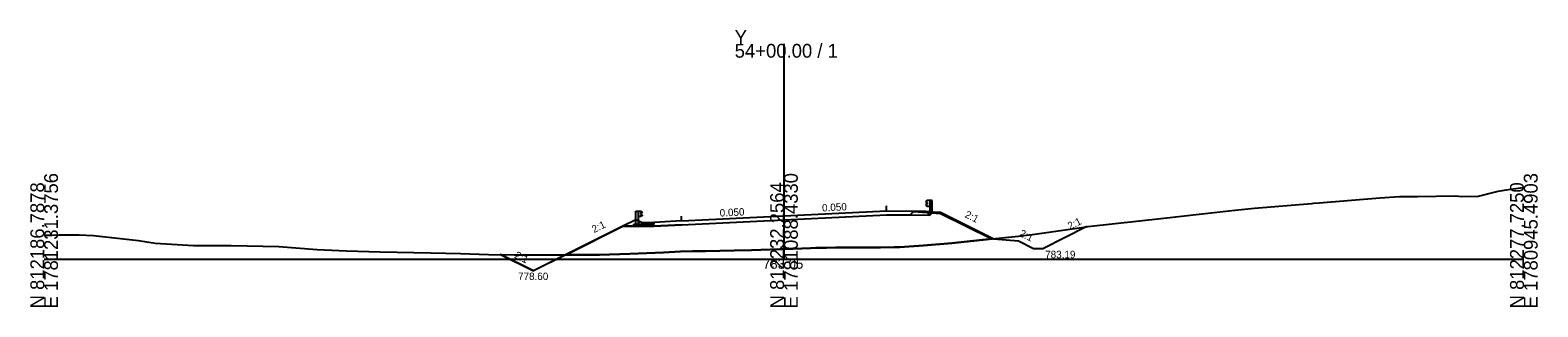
# Model space of a CAD drawing. Extents: x -12583 to 5303, y -44 to 25667.
# Drawn here: x 3997.2 to 4302.8, y 4490.3 to 4546.5 of the extents above; entities that cross this region are included whole.
import ezdxf

# ---------------------------------------------------------------- set-up
doc = ezdxf.new("R2010")
doc.units = 0
for name, color, linetype in [('Exist Cross Section Cell', 7, 'Continuous'), ('Exist XS Center Line Elevation Label', 7, 'Continuous'), ('Exist XS Ground Line', 7, 'Continuous'), ('Prop XS DDE', 7, 'Continuous'), ('Prop XS Ditch Standard Text', 7, 'Continuous'), ('Prop XS Dump Level', 7, 'Continuous'), ('Prop XS Earthwork Shape', 7, 'Continuous'), ('Prop XS EOT Tick Mark', 7, 'Continuous'), ('Prop XS Finish Grade', 7, 'Continuous'), ('Prop XS Finish Grade CurbGutter', 7, 'Continuous'), ('Prop XS Finish Grade Earthwork', 7, 'Continuous'), ('Prop XS Finish Grade Paved Shoulder', 7, 'Continuous'), ('Prop XS Finish Grade Pavement', 7, 'Continuous'), ('Prop XS Guardrail', 7, 'Continuous'), ('Prop XS Pvmt Edge Slope', 7, 'Continuous'), ('Prop XS SE Text', 7, 'Continuous'), ('Prop XS Side Slope Text', 7, 'Continuous'), ('Prop XS Subgrade CurbGutter', 7, 'Continuous'), ('Prop XS Subgrade Earthwork', 7, 'Continuous')]:
    doc.layers.add(name, color=color, linetype=linetype)

msp = doc.modelspace()

# ---------------------------------------------------------------- linework, layer by layer
at = {"layer": 'Exist Cross Section Cell'}
for p, q in [((4150, 4500), (4150, 4543.71)), ((4000, 4500), (4150, 4500)), ((4150, 4500), (4300, 4500))]:
    msp.add_line(p, q, dxfattribs=at)
at = {"layer": 'Exist XS Ground Line'}
for p, q in [((4258.5, 4511.44), (4270.78, 4512.45)), ((4270.78, 4512.45), (4274.82, 4512.74)), ((4274.82, 4512.74), (4278.41, 4512.75)), ((4278.41, 4512.75), (4286.09, 4512.83)), ((4286.09, 4512.83), (4287.59, 4512.75)), ((4287.59, 4512.75), (4290.79, 4512.78)), ((4290.79, 4512.78), (4293.71, 4513.52)), ((4293.71, 4513.52), (4294.79, 4513.81)), ((4294.79, 4513.81), (4296.42, 4514.07)), ((4296.42, 4514.07), (4299.79, 4514.56)), ((4299.79, 4514.56), (4300, 4514.57)), ((4227.01, 4508.35), (4234.17, 4509.11)), ((4234.17, 4509.11), (4241.38, 4509.96)), ((4241.38, 4509.96), (4245.38, 4510.34)), ((4245.38, 4510.34), (4256.97, 4511.31)), ((4256.97, 4511.31), (4257.33, 4511.35)), ((4257.33, 4511.35), (4258.5, 4511.44)), ((4200.83, 4505.09), (4211.23, 4506.59)), ((4211.23, 4506.59), (4211.61, 4506.63)), ((4211.61, 4506.63), (4227.01, 4508.35)), ((4000, 4504.84), (4001.52, 4504.9)), ((4001.52, 4504.9), (4002.98, 4504.96)), ((4002.98, 4504.96), (4004.78, 4504.96)), ((4004.78, 4504.96), (4007.12, 4504.93)), ((4007.12, 4504.93), (4010, 4504.82)), ((4010, 4504.82), (4019.13, 4503.77)), ((4019.13, 4503.77), (4022.49, 4503.22)), ((4022.49, 4503.22), (4030.28, 4502.74)), ((4030.28, 4502.74), (4031.18, 4502.75)), ((4031.18, 4502.75), (4031.7, 4502.74)), ((4031.7, 4502.74), (4037.9, 4502.78)), ((4037.9, 4502.78), (4047.55, 4502.55)), ((4173.46, 4502.42), (4178.27, 4502.78)), ((4178.27, 4502.78), (4184.03, 4503.28)), ((4184.03, 4503.28), (4194.14, 4504.32)), ((4194.14, 4504.32), (4197.53, 4504.66)), ((4197.53, 4504.66), (4200.83, 4505.09)), ((4047.55, 4502.55), (4055.38, 4501.98)), ((4055.38, 4501.98), (4061.29, 4501.66)), ((4061.29, 4501.66), (4068.15, 4501.46)), ((4068.15, 4501.46), (4078.42, 4501.27)), ((4078.42, 4501.27), (4084.4, 4501.12)), ((4084.4, 4501.12), (4090.07, 4500.94)), ((4090.07, 4500.94), (4095.39, 4500.9)), ((4095.39, 4500.9), (4102.78, 4500.88)), ((4102.78, 4500.88), (4109.9, 4500.91)), ((4109.9, 4500.91), (4112.59, 4500.86)), ((4112.59, 4500.86), (4118.75, 4501.1)), ((4118.75, 4501.1), (4125.54, 4501.33)), ((4125.54, 4501.33), (4128.99, 4501.54)), ((4128.99, 4501.54), (4131.45, 4501.61)), ((4131.45, 4501.61), (4134.11, 4501.64)), ((4134.11, 4501.64), (4139.88, 4501.77)), ((4139.88, 4501.77), (4143.39, 4501.84)), ((4143.39, 4501.84), (4149.17, 4502.02)), ((4149.17, 4502.02), (4150, 4502.05)), ((4150, 4502.05), (4155.39, 4502.24)), ((4155.39, 4502.24), (4156.46, 4502.27)), ((4156.46, 4502.27), (4158.63, 4502.31)), ((4158.63, 4502.31), (4160.51, 4502.38)), ((4160.51, 4502.38), (4163.08, 4502.37)), ((4163.08, 4502.37), (4169.57, 4502.36)), ((4169.57, 4502.36), (4172.34, 4502.42)), ((4172.34, 4502.42), (4173.46, 4502.42))]:
    msp.add_line(p, q, dxfattribs=at)
at = {"layer": 'Prop XS DDE'}
for p, q in [((4211.43, 4506.61), (4202.59, 4502.19)), ((4192.51, 4504.15), (4197.51, 4503.73)), ((4197.51, 4503.73), (4200.59, 4502.19)), ((4200.59, 4502.19), (4202.59, 4502.19))]:
    msp.add_line(p, q, dxfattribs=at)
at = {"layer": 'Prop XS Dump Level'}
for p, q in [((4150, 4508.78), (4170.75, 4509.82)), ((4129.25, 4507.75), (4150, 4508.78))]:
    msp.add_line(p, q, dxfattribs=at)
at = {"layer": 'Prop XS Earthwork Shape'}
for points in [[(4181.75, 4509.29), (4192.11, 4504.11), (4184.03, 4503.28), (4178.27, 4502.78), (4173.46, 4502.42), (4172.34, 4502.42), (4169.57, 4502.36), (4163.08, 4502.37), (4160.51, 4502.38), (4158.63, 4502.31), (4156.46, 4502.27), (4155.39, 4502.24), (4150, 4502.05), (4149.17, 4502.02), (4143.39, 4501.84), (4139.88, 4501.77), (4134.11, 4501.64), (4131.45, 4501.61), (4128.99, 4501.54), (4125.54, 4501.33), (4118.75, 4501.1), (4112.59, 4500.86), (4109.9, 4500.91), (4105.77, 4500.89), (4117.32, 4506.67), (4119.19, 4506.67), (4123.58, 4506.67), (4129.29, 4506.95), (4150.04, 4507.99), (4170.77, 4509.03), (4175.55, 4508.98), (4176.24, 4509.68)], [(4102.78, 4500.88), (4105.77, 4500.89), (4099.18, 4497.6), (4092.55, 4500.92), (4095.39, 4500.9)]]:
    msp.add_lwpolyline(points, close=True, dxfattribs=at)
at = {"layer": 'Prop XS EOT Tick Mark'}
for p, q in [((4170.75, 4509.82), (4170.75, 4510.82)), ((4129.25, 4507.75), (4129.25, 4508.75))]:
    msp.add_line(p, q, dxfattribs=at)
at = {"layer": 'Prop XS Finish Grade'}
for p, q in [((4178.75, 4509.74), (4180.24, 4509.64)), ((4119.98, 4508), (4117.32, 4506.67)), ((4120.56, 4507.71), (4119.98, 4508))]:
    msp.add_line(p, q, dxfattribs=at)
at = {"layer": 'Prop XS Finish Grade CurbGutter'}
for p, q in [((4121.25, 4507.37), (4120.56, 4507.71)), ((4123.58, 4507.46), (4121.25, 4507.37))]:
    msp.add_line(p, q, dxfattribs=at)
at = {"layer": 'Prop XS Finish Grade Earthwork'}
for p, q in [((4180.24, 4509.64), (4181.75, 4509.53)), ((4181.75, 4509.53), (4192.51, 4504.15)), ((4117.32, 4506.67), (4099.18, 4497.6)), ((4092.55, 4500.92), (4099.18, 4497.6))]:
    msp.add_line(p, q, dxfattribs=at)
at = {"layer": 'Prop XS Finish Grade Paved Shoulder'}
for p, q in [((4170.75, 4509.82), (4178.75, 4509.74)), ((4129.25, 4507.75), (4123.58, 4507.46))]:
    msp.add_line(p, q, dxfattribs=at)
at = {"layer": 'Prop XS Finish Grade Pavement'}
for p, q in [((4150, 4508.78), (4170.75, 4509.82)), ((4129.25, 4507.75), (4150, 4508.78))]:
    msp.add_line(p, q, dxfattribs=at)
at = {"layer": 'Prop XS Guardrail'}
for p, q in [((4179.07, 4511.91), (4178.78, 4511.71)), ((4179.57, 4511.91), (4179.07, 4511.91)), ((4180.07, 4511.91), (4179.57, 4511.91)), ((4179.57, 4511.91), (4179.57, 4509.41)), ((4180.07, 4509.41), (4180.07, 4511.91)), ((4119.93, 4507.26), (4119.93, 4509.76)), ((4119.93, 4509.76), (4120.43, 4509.76)), ((4120.43, 4509.76), (4120.93, 4509.76)), ((4120.43, 4509.76), (4120.43, 4507.26)), ((4120.93, 4509.76), (4121.22, 4509.56)), ((4121.22, 4509.44), (4120.93, 4509.24)), ((4120.93, 4509.24), (4120.93, 4509.15)), ((4120.93, 4509.15), (4121.22, 4508.95)), ((4121.22, 4508.83), (4120.93, 4508.63)), ((4121.22, 4509.56), (4121.25, 4509.5)), ((4121.25, 4509.5), (4121.22, 4509.44)), ((4121.22, 4508.95), (4121.25, 4508.89)), ((4121.25, 4508.89), (4121.22, 4508.83)), ((4178.78, 4511.71), (4178.75, 4511.65)), ((4178.75, 4511.65), (4178.78, 4511.59)), ((4178.78, 4511.09), (4178.75, 4511.03)), ((4178.75, 4511.03), (4178.78, 4510.97)), ((4178.78, 4511.59), (4179.07, 4511.39)), ((4179.07, 4511.29), (4178.78, 4511.09)), ((4178.78, 4510.97), (4179.07, 4510.77)), ((4179.07, 4511.39), (4179.07, 4511.29)), ((4179.07, 4510.77), (4179.57, 4510.77)), ((4120.93, 4508.63), (4120.43, 4508.63))]:
    msp.add_line(p, q, dxfattribs=at)
at = {"layer": 'Prop XS Pvmt Edge Slope'}
for p, q in [((4178.75, 4509.74), (4179.55, 4508.94)), ((4119.56, 4507.04), (4119.19, 4506.67)), ((4120.56, 4507.04), (4119.56, 4507.04))]:
    msp.add_line(p, q, dxfattribs=at)
at = {"layer": 'Prop XS Subgrade CurbGutter'}
for p, q in [((4120.56, 4507.04), (4120.56, 4507.71)), ((4123.58, 4507.04), (4120.56, 4507.04)), ((4123.58, 4507.46), (4123.58, 4507.04))]:
    msp.add_line(p, q, dxfattribs=at)
at = {"layer": 'Prop XS Subgrade Earthwork'}
for p, q in [((4150.04, 4507.99), (4170.77, 4509.03)), ((4170.77, 4509.03), (4179.55, 4508.94)), ((4179.55, 4508.94), (4180.24, 4509.64)), ((4119.19, 4506.67), (4117.32, 4506.67)), ((4123.58, 4506.67), (4119.19, 4506.67)), ((4129.29, 4506.95), (4123.58, 4506.67)), ((4129.29, 4506.95), (4150.04, 4507.99))]:
    msp.add_line(p, q, dxfattribs=at)

# ---------------------------------------------------------------- texts
at = {"layer": 'Exist Cross Section Cell'}
for s, p in [('Y', (4140, 4543.71)), ('54+00.00 / 1', (4140, 4540.91))]:
    msp.add_text(s, height=2.8, dxfattribs=at).set_placement(p)
for s, p in [('N 812186.7878', (4000, 4490)), ('E 1781231.3756', (4002.8, 4490)), ('N 812232.2564', (4150, 4490)), ('E 1781088.4330', (4152.8, 4490)), ('N 812277.7250', (4300, 4490)), ('E 1780945.4903', (4302.8, 4490))]:
    msp.add_text(s, height=2.8, rotation=90, dxfattribs=at).set_placement(p)
at = {"layer": 'Exist XS Center Line Elevation Label'}
msp.add_text('783.05', height=2, dxfattribs=at).set_placement((4145.74, 4498.05))
at = {"layer": 'Prop XS Ditch Standard Text'}
for s, p in [('783.19', (4202.95, 4500.2)), ('778.60', (4096.08, 4495.77))]:
    msp.add_text(s, height=1.5, dxfattribs=at).set_placement(p)
at = {"layer": 'Prop XS Dump Level'}
msp.add_text('Case2', height=0.04, dxfattribs=at).set_placement((4178.75, 4509.46))
at = {"layer": 'Prop XS SE Text'}
for p in [(4137, 4508.63), (4157.75, 4509.67)]:
    msp.add_text('0.050', height=1.5, rotation=2.8624, dxfattribs=at).set_placement(p)
at = {"layer": 'Prop XS Side Slope Text'}
for rotation, p in [(333.4349, (4186.52, 4508.58)), (26.5651, (4111.49, 4505.28)), (333.4349, (4197.57, 4504.76)), (26.5651, (4207.98, 4505.95)), (333.4349, (4095.22, 4500.33))]:
    msp.add_text('2:1', height=1.5, rotation=rotation, dxfattribs=at).set_placement(p)

doc.saveas('drawing.dxf')
